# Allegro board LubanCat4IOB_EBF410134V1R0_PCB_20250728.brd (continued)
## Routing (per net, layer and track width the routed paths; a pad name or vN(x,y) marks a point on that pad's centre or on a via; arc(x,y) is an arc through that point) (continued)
MDIP0_PHY: length 30.9
  TOP w0.107: v1(109.33,82.17) 109.48,82.02 109.48,80.75 109.88,80.36 115.88,80.36 117.39,81.87 118.07,81.87 118.88,82.68 120.2,82.68 121.6,84.08 121.6,86.39 121.24,86.76 121.1,86.82 121.06,86.96 J15.2
  BOTTOM w0.107: U14.1 109.83,71.41 109.89,71.47 109.89,71.96 109.52,72.33 109.52,81.99 109.35,82.17 v1(109.33,82.17)
MDIP1_PHY: length 31.2
  TOP w0.107: J15.4 118.81,87.85 118.81,88.95 118.28,89.48 117.15,89.48 117.04,89.38 117.04,89.12 117.12,89.04 117.37,89.04 117.73,88.68 117.73,87.25 119,85.98 119,83.78 117.78,82.57 117.1,82.57 115.59,81.06 111.45,81.06 111.15,81.35 111.15,81.98 v1(110.96,82.17)
  BOTTOM w0.107: v1(110.96,82.17) 111.09,82.04 111.09,82.04 111.08,82.03 111.08,71.3 111.03,71.25 U14.4
MDIP2_PHY: length 23
  TOP w0.107: J15.5 117.16,86.17 117.04,86.21 116.95,86.16 116.62,85.83 116.62,83.07 115.3,81.75 112.85,81.75 112.54,82.06 112.54,82.89 v1(112.37,83.06)
  BOTTOM w0.107: v1(112.37,83.06) 112.5,82.93 112.5,76.58 111.78,75.86 111.78,72.21 111.89,72.1 111.89,71.51 111.83,71.45 U14.6
MDIP3_PHY: length 19.6
  TOP w0.107: v1(114.92,83.16) 114.72,82.95 114.21,82.95 114.05,83.12 114.05,85.86 113.58,86.32 113.57,86.37 113.47,86.42 113.41,86.45 113.36,86.45 113.33,86.49 113.28,86.64 J15.8
  BOTTOM w0.107: U14.9 113.03,71.41 113.11,71.49 113.11,72.07 113.38,72.35 113.38,82.23 114.12,82.97 114.73,82.97 v1(114.92,83.16)
MIC1_L: length 30.7
  BOTTOM w0.203: J27.2 55.12,95.16 55.12,91.18 53.98,90.04 53.15,90.04 J27.4 52.2,86.49 J29.1 50.43,81.67 Z8.2 50.43,78.64 C194.1 50.43,78.33 R208.2 49.41,76.2 47.88,76.2 46.86,75.18 46.86,74.29 C176.2
MIC1_R: length 26
  BOTTOM w0.203: C177.2 46.51,73.93 46.51,75.33 47.73,76.55 48.48,76.55 R218.1 49.14,78.33 C194.2 49.14,78.64 Z11.2 49.14,80.74 49.66,81.25 J29.2 48.64,84.45 48.64,89.33 50.37,91.06 52.07,91.06 J27.3 52.7,91.89 J27.5
MIC2_L: length 19.7
  TOP w0.203: R199.2 57.91,82.43 56.99,81.51 49.36,81.51 49.13,81.28 v1(48.37,81.28)
  BOTTOM w0.203: v1(48.37,81.28) 48.13,81.28 46.81,79.96 46.81,77.42 44.96,75.57 44.96,74.16 C178.2
MIC2_R: length 21.5
  TOP w0.203: R201.2 57.14,81.15 49.5,81.15 49,80.64 48.01,80.64 v1(47.37,81.28)
  BOTTOM w0.203: v1(47.37,81.28) 47.37,81.02 46.46,80.11 46.46,77.57 44.6,75.72 44.6,74.06 C179.2
MINIPCIE_3V3: length 57.6
  TOP w0.254: C151.1 92.26,80.9 87.12,80.9 85.35,79.13 C146.1 R172.1
  TOP w0.381: v1(101.22,80.63) 101.2,80.62 J25.39 ; v1(100.2,80.63) 100.4,80.43 J25.41 ; J25.2 119.2,69.58 119.74,69.04 121.05,69.04 121.59,69.58 121.59,72.87 120.75,73.71 119.2,73.71 v1(118.87,74.04) 118.8,74.12 v1(105.21,74.12)
  TOP w0.508: J25.52 96,71.64 v1(95.25,72.39)
  BOTTOM w0.254: 118.88,74.05 R177.1 ; 118.88,74.05 118.88,73.14 119.75,72.27 C158.1 ; 118.88,74.05 v1(118.87,74.04)
  BOTTOM w0.508: 95.26,72.38 v1(95.25,72.39) ; 95.26,72.38 95.26,72.91 96.39,74.04 96.39,75.71 94.63,77.47 94.63,79.87 v1(95.4,80.64) ; 95.26,72.38 C159.1
  vias: v1(100.2,82.03) v1(101.22,82.03) v1(107.06,72.65) v1(107.85,72.64)
MINIPCIE_NWDISABLE: length 77.4
  TOP w0.152: v1(100.08,64.26) 100.08,65.02 101.09,66.04 102.23,66.04 103.76,67.56 R180.2 ; v1(58.65,81.41) 57.28,80.03 J6.42
  ART03 w0.14: v1(58.65,81.41) 58.65,83.21 60.96,85.52 70.51,85.52 71.64,84.39 97.55,84.39 v1(97.79,84.63)
  BOTTOM w0.152: v1(97.79,84.63) 97.28,84.12 97.28,79.5 100.14,76.65 100.14,64.32 v1(100.08,64.26)
MINIPCIE_PWR_EN: length 92.4
  TOP w0.152: v1(75.95,47.27) 73.79,45.11 73.79,26.67 73.48,26.36 63.98,26.36 63.68,26.06 J5.74
  BOTTOM w0.152: v1(75.95,47.27) 75.95,50.11 75.64,50.42 65.79,50.42 63.63,52.58 63.63,72.35 63.4,72.58 63.4,74.06 63.91,74.56 66.22,74.56 67.44,75.78 67.44,76.67 68,77.23 69.29,77.23 72.7,80.64 73.18,80.64 74.55,82.02 74.55,82.17 75.06,82.68 R175.1
MIPI_CSI0_RX_CLK0N: length 101.5
  TOP w0.107: J3.52 33.71,24.55 33.65,24.49 33.65,23.97 arc(33.68,23.9) 33.76,23.87 arc(33.83,23.84) 33.86,23.76 33.86,23.54 arc(33.83,23.47) 33.76,23.44 arc(33.68,23.41) 33.65,23.34 33.65,23.11 arc(33.68,23.04) 33.76,23.01 arc(33.83,22.98) 33.86,22.91 33.86,22.69 arc(33.83,22.62) 33.76,22.59 arc(33.68,22.56) 33.65,22.48 33.65,21.7 33.89,21.46 34.66,21.46 34.86,21.66 v1(34.86,21.68)
  ART03 w0.102: v1(124.02,24.49) 124.21,24.3 124.21,23.97 123.1,22.86 83.45,22.86 82.43,21.84 41.63,21.84 41.07,22.4 37.36,22.4 36.45,21.48 35.45,21.48 35.26,21.68 v1(34.86,21.68)
  BOTTOM w0.107: v1(124.02,24.49) 124.2,24.68 124.2,26.49 124.46,26.75 J23.10
MIPI_CSI0_RX_CLK0P: length 101.5
  TOP w0.107: v1(34.86,21.01) 34.7,21.18 33.78,21.18 33.37,21.58 33.37,24.49 33.31,24.55 J3.50
  ART03 w0.102: v1(34.86,21.01) 35.26,21.01 35.45,21.21 36.56,21.21 37.48,22.12 40.96,22.12 41.51,21.56 82.55,21.56 83.57,22.58 123.22,22.58 124.49,23.85 124.49,24.3 v1(124.68,24.49)
  BOTTOM w0.107: J23.9 125.72,26.25 125.5,26.47 124.58,26.47 124.49,26.37 124.49,24.68 v1(124.68,24.49)
MIPI_CSI0_RX_CLK1N: length 116.4
  TOP w0.107: J3.36 30.51,26.46 v1(30.67,26.62) ; v1(123.95,29.72) 124.13,29.89 124.77,29.89 125.29,29.37 125.54,29.37 125.66,29.25 J24.10
  ART03 w0.102: v1(30.67,26.62) 30.67,27.01 30.48,27.21 30.48,28.47 30.76,28.75 65.43,28.75 65.7,29.02 65.7,30.05 65.8,30.15 66.1,30.15 66.2,30.05 66.2,29.02 66.47,28.75 67.07,28.75 67.34,29.02 67.34,30.83 67.44,30.94 67.74,30.94 67.84,30.83 67.84,29.02 68.11,28.75 68.66,28.75 68.94,29.03 68.94,30.73 69.14,30.94 69.88,30.94 70.08,30.73 70.08,29.14 70.42,28.8 71.4,28.8 71.79,29.19 71.79,30.8 71.91,30.91 72.21,30.91 72.31,30.81 72.31,30.11 72.57,29.84 73.11,29.84 73.37,30.11 73.37,30.81 73.48,30.91 99.72,30.91 102.04,28.59 107.71,28.59 108.1,28.19 115.13,28.19 117.84,30.91 120.2,30.91 arc(120.26,30.88) 120.29,30.82 arc(120.31,30.76) 120.38,30.73 120.61,30.73 arc(120.67,30.76) 120.7,30.82 arc(120.72,30.88) 120.78,30.91 121.01,30.91 arc(121.08,30.88) 121.1,30.82 arc(121.13,30.76) 121.19,30.73 121.42,30.73 arc(121.48,30.76) 121.51,30.82 arc(121.53,30.88) 121.6,30.91 121.86,30.91 122.81,29.96 123.71,29.96 v1(123.95,29.72)
MIPI_CSI0_RX_CLK1P: length 116.4
  TOP w0.107: J3.34 30.11,26.51 v1(30.01,26.62) ; J24.9 125.66,29.75 125.56,29.65 125.41,29.65 124.89,30.18 124.15,30.18 v1(123.95,30.38)
  ART03 w0.102: v1(30.01,26.62) 30.01,27.01 30.2,27.21 30.2,28.59 30.65,29.03 65.32,29.03 65.42,29.13 65.42,30.16 65.68,30.43 66.22,30.43 66.48,30.16 66.48,29.13 66.59,29.03 66.95,29.03 67.06,29.13 67.06,30.95 67.32,31.22 67.86,31.22 68.12,30.95 68.12,29.13 68.22,29.03 68.54,29.03 68.66,29.15 68.66,30.85 69.02,31.22 69.99,31.22 70.36,30.85 70.36,29.26 70.54,29.08 71.28,29.08 71.51,29.31 71.51,30.91 71.79,31.19 72.32,31.19 72.59,30.92 72.59,30.22 72.69,30.12 72.99,30.12 73.09,30.22 73.09,30.92 73.36,31.19 99.83,31.19 102.15,28.87 107.82,28.87 108.22,28.47 115.01,28.47 117.73,31.19 121.97,31.19 122.92,30.24 123.81,30.24 v1(123.95,30.38)
MIPI_CSI0_RX_D0N: length 101.6
  TOP w0.107: J3.62 35.71,24.55 35.65,24.49 35.65,24.06 36.24,23.47 36.88,23.47 arc(36.95,23.5) 36.98,23.57 arc(37.01,23.64) 37.09,23.67 37.31,23.67 arc(37.38,23.64) 37.41,23.57 arc(37.44,23.5) 37.51,23.47 37.74,23.47 arc(37.81,23.5) 37.84,23.57 arc(37.87,23.64) 37.94,23.67 38.16,23.67 arc(38.23,23.64) 38.26,23.57 arc(38.29,23.5) 38.37,23.47 39.01,23.47 39.2,23.66 v1(39.6,23.66)
  ART03 w0.102: v1(39.6,23.66) 40,23.66 40.19,23.47 41.3,23.47 42.08,22.69 72.76,22.69 72.86,22.79 72.86,23.36 73.13,23.62 73.66,23.62 73.93,23.36 73.93,22.79 74.03,22.69 74.34,22.69 74.44,22.79 74.44,23.36 74.7,23.62 75.24,23.62 75.5,23.36 75.5,22.79 75.61,22.69 81.38,22.69 82.71,24.03 122.69,24.03 122.94,24.27 122.94,25.69 123.46,26.21 125.36,26.21 126.78,27.63 127.46,27.63 v1(127.64,27.81)
  BOTTOM w0.107: J23.12 127.25,27.75 127.34,27.66 127.49,27.66 v1(127.64,27.81)
MIPI_CSI0_RX_D0P: length 101.6
  TOP w0.107: J3.60 35.31,24.55 35.37,24.49 35.37,23.94 36.12,23.18 39.01,23.18 39.2,23 v1(39.6,23)
  ART03 w0.102: v1(127.64,27.15) 127.43,27.35 126.9,27.35 125.48,25.93 123.57,25.93 123.22,25.58 123.22,24.15 122.81,23.75 82.83,23.75 81.49,22.41 75.49,22.41 75.22,22.68 75.22,23.24 75.12,23.34 74.82,23.34 74.72,23.24 74.72,22.68 74.45,22.41 73.92,22.41 73.65,22.68 73.65,23.24 73.55,23.34 73.24,23.34 73.14,23.24 73.14,22.68 72.88,22.41 41.96,22.41 41.19,23.19 40.19,23.19 40,23 v1(39.6,23)
  BOTTOM w0.107: J23.11 127.25,27.25 127.32,27.32 127.47,27.32 v1(127.64,27.15)
MIPI_CSI0_RX_D1N: length 101.5
  TOP w0.107: J3.58 34.91,24.55 34.85,24.49 34.85,23.26 36.78,21.33 37.24,21.33 arc(37.32,21.36) 37.35,21.44 arc(37.38,21.51) 37.45,21.54 37.67,21.54 arc(37.74,21.51) 37.77,21.44 arc(37.8,21.36) 37.87,21.33 38.1,21.33 arc(38.17,21.36) 38.2,21.44 arc(38.23,21.51) 38.3,21.54 38.52,21.54 arc(38.6,21.51) 38.63,21.44 arc(38.66,21.36) 38.73,21.33 39.01,21.33 39.2,21.52 v1(39.6,21.52)
  ART03 w0.102: v1(39.6,21.52) 40,21.52 40.19,21.33 40.89,21.33 41.24,20.98 42.62,20.98 42.88,20.71 42.88,20.19 42.98,20.09 43.29,20.09 43.39,20.19 43.39,20.71 43.66,20.98 83.29,20.98 84.4,22.1 123.65,22.1 125.6,24.05 125.6,24.71 126.48,25.59 127.44,25.59 v1(127.64,25.78)
  BOTTOM w0.107: J23.8 127.25,25.75 127.36,25.65 127.5,25.65 v1(127.64,25.78)
MIPI_CSI0_RX_D1P: length 101.5
  TOP w0.107: J3.56 34.51,24.55 34.57,24.49 34.57,23.14 36.66,21.05 39.01,21.05 39.2,20.86 v1(39.6,20.86)
  ART03 w0.102: v1(39.6,20.86) 40,20.86 40.19,21.05 40.77,21.05 41.12,20.7 42.5,20.7 42.6,20.6 42.6,20.08 42.87,19.81 43.41,19.81 43.67,20.08 43.67,20.6 43.77,20.7 83.4,20.7 84.52,21.82 123.76,21.82 125.88,23.94 125.88,24.6 126.6,25.31 127.44,25.31 v1(127.64,25.12)
  BOTTOM w0.107: J23.7 127.25,25.25 127.31,25.3 127.45,25.3 v1(127.64,25.12)
MIPI_CSI0_RX_D2N: length 116.3
  TOP w0.107: J3.46 32.51,26.34 v1(32.79,26.62) ; J24.12 125.66,28.25 125.55,28.36 124.19,28.36 124,28.17 v1(123.95,28.17)
  ART03 w0.102: v1(32.79,26.62) 32.79,27.01 32.64,27.17 32.64,27.61 32.99,27.96 70.59,27.96 70.69,27.86 70.69,26.25 70.96,25.98 71.5,25.98 71.76,26.25 71.76,27.86 71.86,27.96 72.09,27.96 72.19,27.86 72.19,26.27 72.46,26 72.99,26 73.26,26.27 73.26,27.84 73.36,27.94 73.67,27.94 73.77,27.84 73.77,26.27 74.03,26 74.61,26 74.9,26.29 74.9,29.84 75.08,30.02 98.53,30.02 98.73,29.82 98.73,27.54 99,27.28 99.58,27.28 99.85,27.54 99.85,28.73 99.95,28.83 100.26,28.83 100.36,28.73 100.36,27.54 100.62,27.28 115.54,27.28 115.73,27.46 arc(115.82,27.5) 115.92,27.46 arc(116.02,27.42) 116.11,27.46 116.21,27.56 arc(116.25,27.66) 116.21,27.75 arc(116.17,27.85) 116.21,27.94 118.21,29.95 121.38,29.95 122.96,28.37 123.75,28.37 v1(123.95,28.17)
MIPI_CSI0_RX_D2P: length 116.3
  TOP w0.107: J3.44 32.11,26.6 v1(32.13,26.62) ; v1(123.95,28.83) 124.14,28.64 125.55,28.64 125.66,28.75 J24.11
  ART03 w0.102: v1(32.13,26.62) 32.13,27.05 32.36,27.28 32.36,27.72 32.87,28.24 70.71,28.24 70.97,27.97 70.97,26.36 71.08,26.26 71.38,26.26 71.48,26.36 71.48,27.97 71.75,28.24 72.21,28.24 72.47,27.97 72.47,26.38 72.57,26.28 72.88,26.28 72.98,26.38 72.98,27.95 73.25,28.22 73.78,28.22 74.05,27.95 74.05,26.38 74.15,26.28 74.5,26.28 74.63,26.41 74.63,29.96 74.97,30.3 98.65,30.3 99.01,29.93 99.01,27.66 99.12,27.56 99.47,27.56 99.57,27.66 99.57,28.84 99.84,29.11 100.37,29.11 100.64,28.84 100.64,27.66 100.74,27.56 115.43,27.56 118.1,30.22 121.5,30.22 123.07,28.65 123.77,28.65 v1(123.95,28.83)
MIPI_CSI0_RX_D3N: length 116.3
  TOP w0.107: v1(31.84,22.55) 31.84,22.95 31.65,23.13 31.65,24.49 31.71,24.55 J3.42 ; J24.8 127.26,30.25 127.38,30.37 128.1,30.37 v1(128.27,30.2)
  ART03 w0.102: v1(128.27,30.2) 128.08,30.39 126.31,30.39 124.88,31.83 124.62,31.83 arc(124.55,31.8) 124.52,31.72 arc(124.49,31.65) 124.41,31.62 124.21,31.62 arc(124.14,31.65) 124.11,31.72 arc(124.08,31.8) 124.01,31.83 123.8,31.83 arc(123.73,31.8) 123.7,31.72 arc(123.67,31.65) 123.6,31.62 123.4,31.62 arc(123.33,31.65) 123.3,31.72 arc(123.27,31.8) 123.2,31.83 117.23,31.83 114.87,29.46 102.45,29.46 100.19,31.72 66.03,31.72 63.95,29.64 30.47,29.64 29.26,28.44 29.26,24.91 29.46,24.7 31.29,24.7 31.65,24.34 31.65,23.14 31.84,22.94 v1(31.84,22.55)
MIPI_CSI0_RX_D3P: length 116.3
  TOP w0.107: J3.40 31.31,24.55 31.37,24.49 31.37,23.13 31.18,22.95 v1(31.18,22.55) ; v1(128.27,30.86) 128.06,30.65 127.35,30.65 127.26,30.75 J24.7
  ART03 w0.102: v1(31.18,22.55) 31.18,22.94 31.37,23.14 31.37,24.22 31.17,24.42 29.35,24.42 28.98,24.79 28.98,28.55 30.35,29.92 63.83,29.92 65.91,32 100.3,32 102.56,29.74 114.75,29.74 117.12,32.1 124.99,32.1 126.43,30.67 128.08,30.67 v1(128.27,30.86)
MIPI_DPHY0_RX_CLKN: length 128.4
  TOP w0.107: v1(22.5,59.94) 22.5,60.34 22.32,60.53 22.32,65.57 26.45,69.7 26.45,70.95 26.51,71.01 J4.15
  ART03 w0.102: v1(121.54,52.32) 121.39,52.48 121.39,52.53 121.28,52.64 121.28,53.72 119.25,55.75 118.89,55.75 arc(118.82,55.78) 118.8,55.85 arc(118.77,55.91) 118.7,55.94 118.48,55.94 arc(118.42,55.91) 118.39,55.85 arc(118.36,55.78) 118.3,55.75 118.08,55.75 arc(118.01,55.78) 117.98,55.85 arc(117.96,55.91) 117.89,55.94 117.67,55.94 arc(117.6,55.91) 117.58,55.85 arc(117.55,55.78) 117.48,55.75 105.69,55.75 103.91,57.53 85.36,57.53 84.44,56.62 80.47,56.62 78.49,58.6 53.57,58.6 52.2,59.97 46.49,59.97 44.82,58.29 22.75,58.29 22.35,58.69 22.35,59.79 v1(22.5,59.94)
  BOTTOM w0.107: v1(121.54,52.32) 121.31,52.1 121.31,49.45 122.17,48.59 125.5,48.59 125.66,48.75 J21.10
MIPI_DPHY0_RX_CLKP: length 128.3
  TOP w0.107: J4.13 26.11,71.01 26.17,70.95 26.17,69.82 22.03,65.68 22.03,60.53 21.84,60.34 v1(21.84,59.94)
  ART03 w0.102: v1(120.88,52.32) 121.01,52.45 121.01,53.6 119.14,55.47 105.57,55.47 103.8,57.25 85.47,57.25 84.56,56.34 80.35,56.34 78.37,58.32 53.46,58.32 52.09,59.69 46.61,59.69 44.93,58.01 22.63,58.01 22.07,58.57 22.07,59.71 v1(21.84,59.94)
  BOTTOM w0.107: v1(120.88,52.32) 121.03,52.17 121.03,49.33 122.05,48.31 125.6,48.31 125.66,48.25 J21.9
MIPI_DPHY0_RX_D0N: length 128.4
  TOP w0.107: J4.25 28.51,71.01 28.45,70.95 28.45,69.56 25.03,66.13 25.03,63.8 24.74,63.51 24.74,59.68 24.95,59.46 27.05,59.46 27.33,59.19 27.33,58.63 27.05,58.36 25.58,58.36 25.4,58.18 25.4,57.32 25.61,57.11 27.01,57.11 v1(27.18,57.28)
  ART03 w0.102: v1(27.18,57.28) 27.36,57.1 45.18,57.1 46.38,58.29 52.29,58.29 53.22,57.36 74.55,57.36 76.08,55.83 77.68,55.83 77.78,55.93 77.78,56.86 78.05,57.12 78.59,57.12 78.85,56.86 78.85,55.93 78.95,55.83 104.2,55.83 105.12,54.91 117.61,54.91 118.58,53.94 arc(118.65,53.91) 118.73,53.94 arc(118.8,53.98) 118.88,53.94 119.02,53.81 arc(119.05,53.73) 119.02,53.66 arc(118.98,53.58) 119.02,53.5 119.15,53.37 arc(119.23,53.34) 119.3,53.37 arc(119.38,53.4) 119.46,53.37 119.59,53.24 arc(119.62,53.16) 119.59,53.08 arc(119.56,53.01) 119.59,52.93 121.16,51.36 121.16,50.75 121.39,50.53 121.97,50.53 v1(122.19,50.74)
  BOTTOM w0.107: J21.12 125.66,49.75 125.55,49.64 123.75,49.64 122.84,50.55 122.37,50.55 v1(122.19,50.74)
MIPI_DPHY0_RX_D0P: length 128.4
  TOP w0.107: v1(27.18,56.62) 27.18,56.63 26.98,56.83 25.5,56.83 25.12,57.21 25.12,58.3 25.46,58.65 26.93,58.65 27.04,58.75 27.04,59.07 26.93,59.18 24.84,59.18 24.46,59.56 24.46,63.63 24.74,63.92 24.74,66.25 28.17,69.67 28.17,70.95 28.11,71.01 J4.23
  ART03 w0.102: v1(122.19,50.08) 122.02,50.25 121.28,50.25 120.88,50.64 120.88,51.24 117.49,54.63 105,54.63 104.09,55.55 78.84,55.55 78.57,55.81 78.57,56.74 78.47,56.84 78.16,56.84 78.06,56.74 78.06,55.81 77.8,55.55 75.97,55.55 74.44,57.08 53.11,57.08 52.17,58.01 46.49,58.01 45.3,56.82 27.36,56.82 27.18,56.63 v1(27.18,56.62)
  BOTTOM w0.107: v1(122.19,50.08) 122.37,50.27 122.72,50.27 123.63,49.36 125.55,49.36 125.66,49.25 J21.11
MIPI_DPHY0_RX_D1N: length 128.3
  TOP w0.107: v1(24,56.77) 24,57.17 23.8,57.37 23.8,65.97 27.71,69.89 J4.21
  ART03 w0.102: v1(24,56.77) 23.83,56.59 23.83,56.15 23.99,55.99 24.71,55.99 24.81,56.09 24.81,56.82 25.08,57.08 25.61,57.08 25.88,56.82 25.88,56.09 25.98,55.99 45.82,55.99 47.23,57.4 51.73,57.4 52.61,56.52 74.17,56.52 76.09,54.61 104.09,54.61 104.62,54.08 117.37,54.08 120.02,51.43 120.02,51.12 v1(120.21,50.93)
  BOTTOM w0.107: v1(120.21,50.93) 120.04,50.76 120.04,49.22 121.64,47.62 123.58,47.62 arc(123.66,47.65) 123.69,47.73 arc(123.72,47.81) 123.8,47.84 124,47.84 arc(124.08,47.81) 124.12,47.73 arc(124.15,47.65) 124.23,47.62 124.43,47.62 arc(124.51,47.65) 124.54,47.73 arc(124.58,47.81) 124.66,47.84 124.86,47.84 arc(124.94,47.81) 124.97,47.73 arc(125,47.65) 125.08,47.62 125.54,47.62 125.68,47.75 J21.8
MIPI_DPHY0_RX_D1P: length 128.3
  TOP w0.107: v1(23.34,56.77) 23.34,57.17 23.51,57.34 23.51,66.09 27.43,70 27.43,70.89 27.31,71.01 J4.19
  ART03 w0.102: v1(23.34,56.77) 23.55,56.56 23.55,56.03 23.87,55.71 24.82,55.71 25.09,55.97 25.09,56.7 25.19,56.8 25.5,56.8 25.6,56.7 25.6,55.97 25.86,55.71 45.93,55.71 47.35,57.12 51.61,57.12 52.49,56.24 74.06,56.24 75.97,54.33 103.97,54.33 104.51,53.8 117.26,53.8 119.74,51.32 119.74,51.12 v1(119.55,50.93)
  BOTTOM w0.107: J21.7 125.66,47.25 125.58,47.33 121.53,47.33 119.76,49.1 119.76,50.71 v1(119.55,50.93)
MIPI_DPHY0_RX_D2N: length 128.2
  TOP w0.107: J4.9 25.31,71.01 25.25,70.95 25.25,70.08 20.55,65.38 20.55,62.15 v1(20.73,61.97)
  ART03 w0.102: v1(122.81,53.21) 122.58,53.44 122.58,54.96 120.88,56.67 120.21,56.67 arc(120.13,56.7) 120.1,56.77 arc(120.07,56.84) 120,56.87 119.8,56.87 arc(119.73,56.84) 119.69,56.77 arc(119.66,56.7) 119.59,56.67 119.39,56.67 arc(119.32,56.7) 119.29,56.77 arc(119.26,56.84) 119.18,56.87 118.99,56.87 arc(118.91,56.84) 118.88,56.77 arc(118.85,56.7) 118.78,56.67 106.14,56.67 104.31,58.5 85.64,58.5 84.58,59.56 56.87,59.56 56.77,59.66 56.77,60.53 56.51,60.8 55.97,60.8 55.71,60.53 55.71,59.66 55.6,59.56 54.64,59.56 54.44,59.77 54.44,60.49 54.07,60.86 45.7,60.86 43.93,59.08 24.63,59.08 22.9,60.8 20.75,60.8 20.55,61 20.55,61.8 v1(20.73,61.97)
  BOTTOM w0.107: v1(122.81,53.21) 122.63,53.04 122.63,52.63 123.12,52.14 125.57,52.14 125.68,52.25 J21.17
MIPI_DPHY0_RX_D2P: length 128.2
  TOP w0.107: J4.7 24.91,71.01 24.97,70.95 24.97,70.2 20.27,65.5 20.27,62.18 v1(20.07,61.97)
  ART03 w0.102: v1(20.07,61.97) 20.27,61.77 20.27,60.89 20.64,60.52 22.79,60.52 24.51,58.8 44.04,58.8 45.82,60.58 53.95,60.58 54.16,60.37 54.16,59.65 54.52,59.28 55.72,59.28 55.99,59.55 55.99,60.42 56.09,60.52 56.39,60.52 56.49,60.42 56.49,59.55 56.76,59.28 84.46,59.28 85.53,58.22 104.19,58.22 106.02,56.39 120.76,56.39 122.3,54.85 122.3,53.36 v1(122.15,53.21)
  BOTTOM w0.107: v1(122.15,53.21) 122.35,53.01 122.35,52.49 122.99,51.85 125.57,51.85 125.67,51.75 J21.16
MIPI_DPHY0_RX_D3N: length 128.3
  TOP w0.107: J4.5 24.51,71.01 24.45,70.95 24.45,70.5 24.07,70.12 22.88,70.12 22.38,69.62 22.38,68.45 19.56,65.63 19.56,64.51 v1(19.76,64.31)
  ART03 w0.102: v1(124.13,54.23) 123.94,54.42 123.94,55.83 123.42,56.35 122.75,56.35 121.45,57.64 120.76,57.64 arc(120.68,57.68) 120.65,57.76 arc(120.61,57.84) 120.53,57.88 120.36,57.88 arc(120.27,57.84) 120.24,57.76 arc(120.21,57.68) 120.12,57.64 106.6,57.64 104.4,59.84 86.25,59.84 85.45,60.64 60.07,60.64 59.08,61.63 45.22,61.63 43.43,59.84 25.24,59.84 24.16,60.92 24.16,61.06 24.57,61.47 24.57,61.84 24.19,62.22 23.82,62.22 23.35,61.75 23.18,61.75 22.98,61.96 22.98,62.1 23.46,62.58 23.46,62.96 23.08,63.34 22.7,63.34 22.29,62.93 22.15,62.93 21.45,63.63 19.83,63.63 19.56,63.89 19.56,64.11 v1(19.76,64.31)
  BOTTOM w0.107: v1(124.13,54.23) 124.11,54.23 123.85,53.96 123.85,53.68 123.99,53.53 125.49,53.53 125.71,53.75 J21.20
MIPI_DPHY0_RX_D3P: length 128.3
  TOP w0.107: J4.3 24.11,71.01 24.17,70.95 24.17,70.62 23.96,70.41 22.76,70.41 22.09,69.74 22.09,68.57 19.27,65.75 19.27,64.47 19.11,64.31 v1(19.1,64.31)
  ART03 w0.102: v1(123.47,54.23) 123.66,54.42 123.66,55.72 123.31,56.07 122.63,56.07 121.34,57.36 106.48,57.36 104.28,59.56 86.13,59.56 85.33,60.36 59.96,60.36 58.96,61.36 45.34,61.36 43.55,59.56 25.12,59.56 23.88,60.8 23.88,61.18 24.29,61.58 24.29,61.73 24.08,61.94 23.93,61.94 23.46,61.47 23.07,61.47 22.7,61.84 22.7,62.22 23.18,62.7 23.18,62.84 22.96,63.06 22.82,63.06 22.41,62.65 22.03,62.65 21.34,63.35 19.71,63.35 19.28,63.78 19.28,64.13 v1(19.1,64.31)
  BOTTOM w0.107: J21.19 123.88,53.25 123.57,53.56 123.57,54.13 v1(123.47,54.23)
MIPI_DPHY0_TX_CLKN: length 125.2
  TOP w0.107: v1(27.59,62.38) 27.99,62.38 28.18,62.57 28.54,62.57 28.81,62.84 28.81,66.12 31.65,68.97 31.65,70.95 31.71,71.01 J4.41
  ART03 w0.102: v1(128.91,69.7) 128.71,69.89 127.45,69.89 125.23,67.66 93.27,67.66 92.87,67.26 92.87,64.61 92.53,64.27 68.78,64.27 68.51,64.53 68.51,65.23 68.41,65.33 68.11,65.33 68.01,65.23 68.01,64.53 67.74,64.27 67.2,64.27 66.94,64.53 66.94,65.23 66.84,65.33 66.53,65.33 66.43,65.23 66.43,64.53 66.17,64.27 64.19,64.27 63.93,64.53 63.93,65.05 63.83,65.16 63.52,65.16 63.42,65.05 63.42,64.53 63.15,64.27 62.42,64.27 61.78,64.91 48.3,64.91 48,64.61 32.1,64.61 30.07,62.58 27.8,62.58 v1(27.59,62.38)
  BOTTOM w0.107: J19.24 127.31,69.74 127.43,69.86 128.74,69.86 v1(128.91,69.7)
MIPI_DPHY0_TX_CLKP: length 125.3
  TOP w0.107: J4.39 31.31,71.01 31.37,70.95 31.37,69.09 28.52,66.24 28.52,62.96 28.42,62.85 28.18,62.85 27.99,63.04 v1(27.59,63.04)
  ART03 w0.102: v1(27.59,63.04) 27.76,62.86 29.96,62.86 31.98,64.89 47.88,64.89 48.18,65.19 61.9,65.19 62.54,64.55 63.04,64.55 63.14,64.65 63.14,65.17 63.41,65.43 63.94,65.43 64.21,65.17 64.21,64.65 64.31,64.55 66.05,64.55 66.15,64.65 66.15,65.35 66.42,65.61 66.95,65.61 67.22,65.35 67.22,64.65 67.32,64.55 67.63,64.55 67.73,64.65 67.73,65.35 67.99,65.61 68.53,65.61 68.79,65.35 68.79,64.65 68.9,64.55 92.41,64.55 92.59,64.72 92.59,67.38 93.15,67.94 118.8,67.94 arc(118.88,67.98) 118.91,68.05 arc(118.94,68.13) 119.02,68.16 119.21,68.16 arc(119.28,68.13) 119.31,68.05 arc(119.35,67.98) 119.42,67.94 119.61,67.94 arc(119.69,67.98) 119.72,68.05 arc(119.75,68.13) 119.83,68.16 120.02,68.16 arc(120.1,68.13) 120.13,68.05 arc(120.16,67.98) 120.24,67.94 125.12,67.94 127.34,70.17 128.71,70.17 v1(128.91,70.36)
  BOTTOM w0.107: v1(128.91,70.36) 128.7,70.15 127.4,70.15 127.31,70.24 J19.23
MIPI_DPHY0_TX_D0N: length 125.2
  TOP w0.107: J4.51 33.71,71.01 33.65,70.95 33.65,68.56 31.88,66.78 31.88,62.29 v1(32.06,62.1)
  ART03 w0.102: v1(32.06,62.1) 31.89,62.28 31.89,63.31 32,63.42 32.8,63.42 32.93,63.29 32.93,61.76 33.24,61.46 34.01,61.46 34.43,61.87 34.43,63.43 34.64,63.64 35.29,63.64 35.48,63.45 35.48,61.81 35.85,61.44 36.81,61.44 37.18,61.81 37.18,63.21 37.31,63.34 40.76,63.34 41.34,63.92 60.84,63.92 61.91,62.85 68.48,62.85 68.9,63.27 87.92,63.27 88.02,63.17 88.02,62.51 88.29,62.25 88.82,62.25 89.09,62.51 89.09,63.17 89.19,63.27 93.43,63.27 93.9,63.75 93.9,66.18 94.11,66.38 99.65,66.38 100,66.73 107.5,66.73 108,66.23 113.33,66.23 113.69,66.58 121.14,66.58 arc(121.21,66.55) 121.24,66.48 arc(121.27,66.41) 121.34,66.38 121.54,66.38 arc(121.61,66.41) 121.64,66.48 arc(121.67,66.55) 121.75,66.58 121.95,66.58 arc(122.02,66.55) 122.05,66.48 arc(122.08,66.41) 122.15,66.38 122.36,66.38 arc(122.43,66.41) 122.46,66.48 arc(122.49,66.55) 122.56,66.58 125.65,66.58 127.42,68.35 128.71,68.35 v1(128.91,68.16)
  BOTTOM w0.107: J19.27 127.31,68.24 127.41,68.35 128.71,68.35 v1(128.91,68.16)
MIPI_DPHY0_TX_D0P: length 125.2
  TOP w0.107: J4.49 33.31,71.01 33.37,70.95 33.37,68.68 31.59,66.9 31.59,62.29 v1(31.4,62.1)
  ART03 w0.102: v1(31.4,62.1) 31.61,62.31 31.61,63.42 31.89,63.7 32.91,63.7 33.21,63.4 33.21,61.88 33.36,61.74 33.9,61.74 34.15,61.98 34.15,63.55 34.52,63.92 35.4,63.92 35.76,63.57 35.76,61.92 35.96,61.72 36.7,61.72 36.9,61.92 36.9,63.33 37.2,63.62 40.64,63.62 41.22,64.2 60.96,64.2 62.03,63.13 68.37,63.13 68.78,63.55 88.04,63.55 88.3,63.28 88.3,62.63 88.4,62.53 88.71,62.53 88.81,62.63 88.81,63.28 89.07,63.55 93.31,63.55 93.62,63.86 93.62,66.3 93.99,66.66 99.54,66.66 99.88,67.01 107.61,67.01 108.12,66.51 113.22,66.51 113.57,66.86 125.54,66.86 127.3,68.63 128.71,68.63 v1(128.91,68.82)
  BOTTOM w0.107: J19.26 127.31,68.74 127.41,68.64 128.72,68.64 v1(128.91,68.82)
MIPI_DPHY0_TX_D1N: length 125.3
  TOP w0.107: v1(30.48,64.13) 30.48,64.53 30.29,64.72 30.29,66.3 32.85,68.87 32.85,70.95 32.91,71.01 J4.47
  ART03 w0.102: v1(128.91,71.22) 128.74,71.39 127.41,71.39 124.78,68.76 124.4,68.76 arc(124.32,68.73) 124.28,68.65 arc(124.25,68.56) 124.17,68.53 123.99,68.53 arc(123.91,68.56) 123.88,68.65 arc(123.84,68.73) 123.76,68.76 123.59,68.76 arc(123.5,68.73) 123.47,68.65 arc(123.44,68.56) 123.35,68.53 123.18,68.53 arc(123.1,68.56) 123.06,68.65 arc(123.03,68.73) 122.95,68.76 91.74,68.76 91.4,68.42 91.4,65.5 91.13,65.23 87.16,65.23 86.9,65.5 86.9,65.83 86.79,65.93 86.45,65.93 86.35,65.83 86.35,65.44 86.09,65.18 85.55,65.18 85.28,65.44 85.28,65.89 85.22,65.95 84.88,65.95 84.78,65.85 84.78,65.44 84.51,65.18 83.98,65.18 83.71,65.44 83.71,65.88 83.64,65.95 83.3,65.95 83.2,65.85 83.2,65.44 82.94,65.18 82.4,65.18 82.14,65.44 82.14,65.86 82.07,65.92 81.73,65.92 81.63,65.82 81.63,65.44 81.36,65.18 80.83,65.18 80.56,65.44 80.56,65.83 80.49,65.89 80.15,65.89 80.05,65.79 80.05,65.44 79.79,65.18 78.91,65.18 78.65,65.44 78.65,65.86 78.58,65.93 78.24,65.93 78.14,65.83 78.14,65.44 77.88,65.18 77.34,65.18 77.07,65.44 77.07,65.84 76.97,65.94 76.7,65.94 76.6,65.84 76.6,65.5 76.34,65.23 75.57,65.23 75.3,65.5 75.3,65.79 75.2,65.89 74.89,65.89 74.79,65.79 74.79,65.5 74.53,65.23 69.85,65.23 69.02,66.06 30.51,66.06 30.28,65.84 30.28,64.34 v1(30.48,64.13)
  BOTTOM w0.107: v1(128.91,71.22) 128.75,71.38 127.44,71.38 127.31,71.24 J19.21
MIPI_DPHY0_TX_D1P: length 125.2
  TOP w0.107: v1(29.82,64.13) 29.82,64.53 30.01,64.72 30.01,66.42 32.57,68.98 32.57,70.95 32.51,71.01 J4.45
  ART03 w0.102: v1(128.91,71.88) 128.69,71.67 127.29,71.67 124.67,69.04 91.63,69.04 91.12,68.53 91.12,65.61 91.02,65.51 87.28,65.51 87.17,65.61 87.17,65.94 86.91,66.21 86.34,66.21 86.07,65.94 86.07,65.56 85.97,65.45 85.67,65.45 85.56,65.56 85.56,66 85.33,66.23 84.76,66.23 84.5,65.97 84.5,65.56 84.4,65.45 84.09,65.45 83.99,65.56 83.99,66 83.76,66.23 83.19,66.23 82.92,65.96 82.92,65.56 82.82,65.45 82.52,65.45 82.41,65.56 82.41,65.97 82.18,66.2 81.61,66.2 81.35,65.94 81.35,65.56 81.25,65.45 80.94,65.45 80.84,65.56 80.84,65.94 80.61,66.17 80.04,66.17 79.77,65.91 79.77,65.56 79.67,65.45 79.03,65.45 78.93,65.56 78.93,65.98 78.7,66.21 78.13,66.21 77.86,65.94 77.86,65.56 77.76,65.45 77.46,65.45 77.35,65.56 77.35,65.95 77.09,66.22 76.59,66.22 76.32,65.95 76.32,65.61 76.22,65.51 75.68,65.51 75.58,65.61 75.58,65.91 75.31,66.17 74.78,66.17 74.51,65.91 74.51,65.61 74.41,65.51 69.97,65.51 69.13,66.34 30.39,66.34 30,65.95 30,64.31 v1(29.82,64.13)
  BOTTOM w0.107: J19.20 127.31,71.74 127.39,71.66 128.69,71.66 v1(128.91,71.88)
MIPI_DPHY0_TX_D2N: length 125.2
  TOP w0.107: J4.35 30.51,71.01 30.45,70.95 30.45,69.06 27.27,65.88 27.27,64.72 27.46,64.53 v1(27.46,64.13)
  ART03 w0.102: v1(27.46,64.13) 27.3,64.29 27.3,67.22 27.43,67.34 27.74,67.34 27.84,67.24 27.84,65.78 28.1,65.51 28.64,65.51 28.91,65.78 28.91,67.24 29.01,67.34 46.03,67.34 46.78,68.08 49.82,68.08 50.44,67.47 69.23,67.47 70.05,66.64 87.66,66.64 87.96,66.34 90.01,66.34 90.46,66.8 90.46,69.4 90.92,69.85 96.02,69.85 96.5,70.33 122.54,70.33 arc(122.61,70.3) 122.64,70.23 arc(122.67,70.16) 122.74,70.13 122.95,70.13 arc(123.02,70.16) 123.05,70.23 arc(123.08,70.3) 123.15,70.33 123.35,70.33 arc(123.42,70.3) 123.45,70.23 arc(123.48,70.16) 123.56,70.13 123.76,70.13 arc(123.83,70.16) 123.86,70.23 arc(123.89,70.3) 123.96,70.33 124.91,70.33 127.43,72.85 128.71,72.85 v1(128.91,72.66)
  BOTTOM w0.107: J19.18 127.31,72.74 127.41,72.85 128.72,72.85 v1(128.91,72.66)
MIPI_DPHY0_TX_D2P: length 125.3
  TOP w0.107: v1(26.8,64.13) 26.8,64.53 26.98,64.72 26.98,65.99 30.17,69.18 30.17,70.95 30.11,71.01 J4.33
  ART03 w0.102: v1(128.91,73.32) 128.71,73.13 127.32,73.13 124.8,70.61 96.38,70.61 95.9,70.13 90.8,70.13 90.19,69.51 90.19,66.91 89.9,66.62 88.07,66.62 87.77,66.92 70.16,66.92 69.34,67.75 50.55,67.75 49.94,68.36 46.66,68.36 45.92,67.62 28.89,67.62 28.63,67.35 28.63,65.89 28.52,65.79 28.22,65.79 28.12,65.89 28.12,67.35 27.85,67.62 27.31,67.62 27.03,67.33 27.03,64.36 v1(26.8,64.13)
  BOTTOM w0.107: J19.17 127.31,73.24 127.41,73.14 128.72,73.14 v1(128.91,73.32)
MIPI_DPHY0_TX_D3N: length 125.2
  TOP w0.107: v1(26.7,60.96) 26.7,61.36 26.51,61.54 26.51,63.28 25.96,63.83 25.96,65.63 29.71,69.39 J4.31
  ART03 w0.102: v1(128.91,66.63) 128.71,66.82 127.28,66.82 125.74,65.28 119.14,65.28 arc(119.07,65.25) 119.04,65.18 arc(119.01,65.1) 118.94,65.07 118.74,65.07 arc(118.66,65.1) 118.63,65.18 arc(118.6,65.25) 118.53,65.28 118.33,65.28 arc(118.26,65.25) 118.23,65.18 arc(118.2,65.1) 118.13,65.07 117.92,65.07 arc(117.85,65.1) 117.82,65.18 arc(117.79,65.25) 117.72,65.28 108.14,65.28 107.64,64.77 95.13,64.77 94.84,64.48 94.84,61.88 94.33,61.37 87.63,61.37 87.05,61.95 70.47,61.95 69.93,61.41 61.61,61.41 60.15,62.86 41.89,62.86 41.51,62.48 41.51,61.73 40.45,60.67 28.27,60.67 27.37,61.57 26.6,61.57 26.5,61.47 26.5,61.15 v1(26.7,60.96)
  BOTTOM w0.107: v1(128.91,66.63) 128.7,66.83 127.39,66.83 127.31,66.74 J19.30
MIPI_DPHY0_TX_D3P: length 125.2
  TOP w0.107: J4.29 29.31,71.01 29.43,70.89 29.43,69.5 25.67,65.75 25.67,63.71 26.22,63.16 26.22,61.54 26.04,61.36 v1(26.04,60.96)
  ART03 w0.102: v1(128.91,67.29) 128.71,67.1 127.17,67.1 125.63,65.56 108.02,65.56 107.52,65.05 95.02,65.05 94.56,64.6 94.56,61.99 94.21,61.64 87.75,61.64 87.16,62.23 70.35,62.23 69.81,61.69 61.72,61.69 60.26,63.14 41.77,63.14 41.23,62.6 41.23,61.84 40.34,60.95 28.38,60.95 27.48,61.85 26.49,61.85 26.22,61.58 26.22,61.15 v1(26.04,60.96)
  BOTTOM w0.107: v1(128.91,67.29) 128.73,67.11 127.44,67.11 127.31,67.24 J19.29
MIPI_DPHY1_RX_CLKN: length 125.2
  TOP w0.107: J4.87 40.91,71.01 40.85,70.95 40.85,69.68 39.06,67.89 37.54,67.89 35.77,66.12 35.77,53.93 arc(35.8,53.84) 35.89,53.8 arc(35.98,53.77) 36.01,53.68 36.01,53.5 arc(35.98,53.41) 35.89,53.38 arc(35.8,53.34) 35.77,53.26 35.77,52.91 v1(35.97,52.7) ; v1(124.56,50.3) 124.4,50.46 124.4,51.75 124.61,51.96 124.93,51.96 125.64,51.25 J22.10
  ART03 w0.102: v1(124.56,50.3) 124.36,50.1 124.36,49.14 123.93,48.72 119.66,48.72 115.71,52.67 114.86,52.67 114.76,52.57 114.76,51.92 114.49,51.66 113.96,51.66 113.69,51.92 113.69,52.57 113.59,52.67 113.28,52.67 113.18,52.57 113.18,51.99 112.92,51.72 112.38,51.72 112.12,51.99 112.12,52.57 112.01,52.67 111.71,52.67 111.61,52.57 111.61,52 111.34,51.74 110.81,51.74 110.54,52 110.54,52.57 110.44,52.67 75.77,52.67 73.6,54.84 47.79,54.84 47.3,54.35 35.98,54.35 35.68,54.06 35.68,53 v1(35.97,52.7)
MIPI_DPHY1_RX_CLKP: length 125.2
  TOP w0.107: J4.85 40.51,71.01 40.57,70.95 40.57,69.8 38.94,68.17 37.42,68.17 35.48,66.24 35.48,52.88 v1(35.31,52.7) ; v1(123.9,50.3) 123.95,50.36 124.01,50.36 124.11,50.46 124.11,51.86 124.49,52.24 125.05,52.24 125.54,51.75 J22.9
  ART03 w0.102: v1(35.31,52.7) 35.4,52.79 35.4,54.17 35.86,54.63 47.19,54.63 47.67,55.12 73.72,55.12 75.89,52.95 110.55,52.95 110.82,52.68 110.82,52.12 110.92,52.02 111.23,52.02 111.33,52.12 111.33,52.68 111.59,52.95 112.13,52.95 112.39,52.68 112.39,52.1 112.5,52 112.8,52 112.9,52.1 112.9,52.68 113.17,52.95 113.7,52.95 113.97,52.68 113.97,52.04 114.07,51.94 114.38,51.94 114.48,52.04 114.48,52.68 114.74,52.95 115.82,52.95 119.77,49 123.82,49 124.08,49.26 124.08,50.12 v1(123.9,50.3)
MIPI_DPHY1_RX_D0N: length 125.3
  TOP w0.107: v1(127.95,48.9) 128.14,49.09 128.14,50.14 127.92,50.35 127.31,50.35 127.21,50.25 J22.12 ; J4.95 42.51,71.01 42.45,70.95 42.45,69 39.88,66.42 38.96,66.42 38.31,65.76 38.31,61.99 arc(38.34,61.91) 38.43,61.87 arc(38.51,61.84) 38.55,61.75 38.55,61.56 arc(38.51,61.48) 38.43,61.44 arc(38.34,61.41) 38.31,61.33 38.31,61.14 arc(38.34,61.05) 38.43,61.02 arc(38.51,60.98) 38.55,60.9 38.55,60.71 arc(38.51,60.63) 38.43,60.59 arc(38.34,60.56) 38.31,60.47 38.31,60.28 arc(38.34,60.2) 38.43,60.16 arc(38.51,60.13) 38.55,60.05 38.55,59.86 arc(38.51,59.77) 38.43,59.74 arc(38.34,59.7) 38.31,59.62 38.31,59.43 arc(38.34,59.35) 38.43,59.31 arc(38.51,59.28) 38.55,59.19 38.55,59 arc(38.51,58.92) 38.43,58.88 arc(38.34,58.85) 38.31,58.77 38.31,55.98 39.32,54.96 39.32,54.15 arc(39.36,54.04) 39.47,54 arc(39.58,53.96) 39.62,53.85 39.62,53.73 arc(39.58,53.62) 39.47,53.57 arc(39.36,53.53) 39.32,53.42 39.32,52.91 v1(39.53,52.7)
  ART03 w0.102: v1(39.53,52.7) 39.29,52.46 39.29,52.3 39.44,52.15 42.58,52.15 43.39,52.96 72.43,52.96 74.26,51.13 101.74,51.13 102.04,50.83 102.04,50.27 102.14,50.16 102.79,50.16 102.89,50.27 102.89,50.97 103.16,51.24 103.7,51.24 103.96,50.97 103.96,50.27 104.06,50.16 104.37,50.16 104.47,50.27 104.47,51.02 104.73,51.29 105.27,51.29 105.54,51.02 105.54,50.27 105.64,50.16 105.94,50.16 106.04,50.27 106.04,51.07 106.31,51.33 106.85,51.33 107.11,51.07 107.11,50.27 107.21,50.16 116.55,50.16 119.34,47.37 127.46,47.37 128.1,48.02 128.1,48.75 v1(127.95,48.9)
MIPI_DPHY1_RX_D0P: length 125.2
  TOP w0.107: J22.11 127.17,50.75 127.28,50.64 128.04,50.64 128.42,50.26 128.42,49.09 v1(128.61,48.9) ; J4.93 42.11,71.01 42.17,70.95 42.17,69.11 39.76,66.7 38.85,66.7 38.02,65.88 38.02,55.86 39.03,54.85 39.03,52.87 v1(38.87,52.7)
  ART03 w0.102: v1(128.61,48.9) 128.38,48.68 128.38,47.9 127.57,47.09 119.22,47.09 116.43,49.88 107.1,49.88 106.83,50.15 106.83,50.95 106.73,51.05 106.43,51.05 106.32,50.95 106.32,50.15 106.06,49.88 105.52,49.88 105.26,50.15 105.26,50.91 105.16,51.01 104.85,51.01 104.75,50.91 104.75,50.15 104.48,49.88 103.95,49.88 103.68,50.15 103.68,50.85 103.58,50.96 103.28,50.96 103.17,50.85 103.17,50.15 102.91,49.88 102.03,49.88 101.76,50.15 101.76,50.71 101.63,50.85 74.14,50.85 72.31,52.68 43.51,52.68 42.7,51.87 39.32,51.87 39.01,52.18 39.01,52.56 v1(38.87,52.7)
MIPI_DPHY1_RX_D1N: length 125.2
  TOP w0.107: v1(37.72,53.4) 37.56,53.24 37.19,53.24 37.08,53.34 37.08,53.85 arc(37.12,53.94) 37.21,53.98 arc(37.31,54.01) 37.34,54.11 37.34,54.27 arc(37.31,54.37) 37.21,54.4 arc(37.12,54.44) 37.08,54.53 37.08,55.42 arc(37.12,55.51) 37.21,55.54 arc(37.3,55.58) 37.33,55.67 37.33,55.85 arc(37.3,55.94) 37.21,55.97 arc(37.12,56.01) 37.08,56.1 37.08,56.27 arc(37.12,56.36) 37.21,56.4 arc(37.3,56.43) 37.33,56.52 37.33,56.7 arc(37.3,56.79) 37.21,56.82 arc(37.12,56.86) 37.08,56.95 37.08,57.13 arc(37.12,57.22) 37.21,57.25 arc(37.3,57.29) 37.33,57.38 37.33,57.55 arc(37.3,57.64) 37.21,57.68 arc(37.12,57.71) 37.08,57.8 37.08,57.98 arc(37.12,58.07) 37.21,58.11 arc(37.3,58.14) 37.33,58.23 37.33,58.41 arc(37.3,58.5) 37.21,58.53 arc(37.12,58.57) 37.08,58.66 37.08,65.85 38.43,67.19 39.63,67.19 41.65,69.21 41.65,70.95 41.71,71.01 J4.91 ; v1(128.18,52.02) 127.93,52.27 126.48,52.27 J22.8
  ART03 w0.102: v1(37.72,53.4) 37.93,53.19 38.2,53.19 38.73,53.72 73.56,53.72 75.26,52.02 107.73,52.02 108.04,51.71 108.04,51.22 108.18,51.08 108.79,51.08 108.89,51.18 108.89,51.85 109.16,52.11 109.69,52.11 109.96,51.85 109.96,51.18 110.06,51.08 116.68,51.08 119.6,48.16 125.04,48.16 125.25,48.36 125.25,49.16 125.61,49.53 126.75,49.53 126.85,49.63 126.85,49.94 126.75,50.04 126.24,50.04 125.92,50.35 125.92,50.95 126.26,51.28 127.21,51.28 arc(127.29,51.32) 127.33,51.4 arc(127.36,51.48) 127.44,51.51 127.62,51.51 arc(127.7,51.48) 127.73,51.4 arc(127.77,51.32) 127.85,51.28 128.17,51.28 128.36,51.47 128.36,51.84 v1(128.18,52.02)
MIPI_DPHY1_RX_D1P: length 125.2
  TOP w0.107: J4.89 41.31,71.01 41.37,70.95 41.37,69.33 39.52,67.48 38.31,67.48 36.8,65.96 36.8,53.23 37.07,52.95 37.51,52.95 v1(37.72,52.74) ; J22.7 127.18,52.75 127.37,52.56 128.06,52.56 v1(128.18,52.68)
  ART03 w0.102: v1(37.72,52.74) 37.89,52.91 38.32,52.91 38.85,53.44 73.44,53.44 75.14,51.74 107.62,51.74 107.76,51.59 107.76,51.1 108.07,50.8 108.91,50.8 109.17,51.06 109.17,51.73 109.27,51.84 109.58,51.84 109.68,51.73 109.68,51.06 109.95,50.8 116.56,50.8 119.48,47.88 125.16,47.88 125.53,48.24 125.53,49.05 125.73,49.25 126.87,49.25 127.13,49.51 127.13,50.05 126.87,50.32 126.35,50.32 126.2,50.47 126.2,50.83 126.38,51 128.29,51 128.64,51.35 128.64,52.22 v1(128.18,52.68)
MIPI_DPHY1_RX_D2N: length 125.1
  TOP w0.107: v1(121.52,45.67) 121.36,45.83 121.36,47.39 121.81,47.85 122.15,47.85 arc(122.23,47.81) 122.26,47.73 arc(122.3,47.65) 122.38,47.62 122.58,47.62 arc(122.66,47.65) 122.69,47.73 arc(122.73,47.81) 122.81,47.85 123,47.85 arc(123.08,47.81) 123.12,47.73 arc(123.15,47.65) 123.23,47.62 123.43,47.62 arc(123.51,47.65) 123.54,47.73 arc(123.58,47.81) 123.66,47.85 125.39,47.85 125.49,47.75 J22.17 ; J4.83 40.11,71.01 40.05,70.95 40.05,69.93 38.71,68.59 36.61,68.59 34.53,66.51 34.53,54.45 33.83,53.75 33.83,52.9 v1(34.03,52.7)
  ART03 w0.102: v1(121.52,45.67) 121.38,45.81 121.38,46.21 121.03,46.56 119.02,46.56 116.3,49.27 101.16,49.27 101.06,49.38 101.06,49.91 100.8,50.17 100.26,50.17 99.99,49.91 99.99,49.38 99.89,49.27 99.59,49.27 99.49,49.38 99.49,49.97 99.21,50.26 98.68,50.26 98.42,49.99 98.42,49.53 98.32,49.43 74.27,49.43 71.63,52.07 43.69,52.07 43.05,51.43 34.21,51.43 33.82,51.83 33.82,52.49 v1(34.03,52.7)
MIPI_DPHY1_RX_D2P: length 125.1
  TOP w0.107: J4.81 39.71,71.01 39.77,70.95 39.77,70.05 38.59,68.87 36.49,68.87 34.24,66.63 34.24,54.56 33.55,53.87 33.55,52.88 v1(33.37,52.7) ; v1(120.86,45.67) 121.07,45.89 121.07,47.51 121.69,48.13 125.4,48.13 125.52,48.25 J22.16
  ART03 w0.102: v1(33.37,52.7) 33.54,52.54 33.54,51.72 34.1,51.15 43.17,51.15 43.8,51.79 71.52,51.79 74.16,49.15 98.43,49.15 98.7,49.41 98.7,49.87 98.8,49.98 99.09,49.98 99.21,49.86 99.21,49.26 99.47,49 100.01,49 100.27,49.26 100.27,49.79 100.38,49.89 100.68,49.89 100.78,49.79 100.78,49.26 101.05,49 116.19,49 118.9,46.28 120.92,46.28 121.1,46.1 121.1,45.91 v1(120.86,45.67)
MIPI_DPHY1_RX_D3N: length 125.2
  TOP w0.107: J4.79 39.31,71.01 39.25,70.95 39.25,70.12 38.42,69.29 35.95,69.29 33.26,66.59 33.26,65.18 arc(33.29,65.1) 33.37,65.06 arc(33.45,65.03) 33.49,64.95 33.49,64.75 arc(33.45,64.67) 33.37,64.64 arc(33.29,64.6) 33.26,64.52 33.26,64.32 arc(33.29,64.24) 33.37,64.21 arc(33.45,64.18) 33.49,64.1 33.49,63.9 arc(33.45,63.82) 33.37,63.78 arc(33.29,63.75) 33.26,63.67 33.26,55.97 32.1,54.81 32.1,52.86 v1(32.26,52.7) ; J22.20 125.45,46.25 125.24,46.47 123.93,46.47 123.2,45.73 123.2,44.34 v1(123.34,44.19)
  ART03 w0.102: v1(32.26,52.7) 32.07,52.51 32.07,51.88 33.3,50.65 43.46,50.65 43.99,51.18 70.6,51.18 73.39,48.39 116.1,48.39 119.33,45.16 122.81,45.16 123.16,44.8 123.16,44.37 v1(123.34,44.19)
MIPI_DPHY1_RX_D3P: length 125.2
  TOP w0.107: J22.19 123.81,46.75 122.91,45.85 122.91,44.42 v1(122.68,44.19) ; v1(31.6,52.7) 31.82,52.92 31.82,54.93 32.97,56.09 32.97,66.71 35.83,69.57 38.3,69.57 38.97,70.24 38.97,70.95 38.91,71.01 J4.77
  ART03 w0.102: v1(122.68,44.19) 122.89,44.4 122.89,44.68 122.69,44.88 119.22,44.88 115.99,48.11 73.28,48.11 70.48,50.9 44.11,50.9 43.58,50.37 33.18,50.37 31.79,51.76 31.79,52.51 v1(31.6,52.7)
MIPI_DPHY1_TX_CLKN: length 108.8
  TOP w0.107: J4.65 36.51,72.2 36.45,72.26 36.45,73.25 36.64,73.44 v1(36.64,73.84) ; v1(128.89,78.43) 128.89,78.42 128.66,78.19 127.36,78.19 127.31,78.25 J20.24
  ART03 w0.102: v1(36.64,73.84) 36.64,73.44 36.45,73.25 36.45,71.64 36.66,71.43 40.53,71.43 40.75,71.65 40.75,72.45 41.02,72.71 41.53,72.71 41.82,72.42 41.82,71.65 41.92,71.55 72.42,71.55 72.78,71.19 72.78,70.59 73.01,70.36 84.06,70.36 84.26,70.56 84.26,74.27 84.63,74.64 92.87,74.64 93.48,74.03 97.75,74.03 98.51,74.8 117.9,74.8 119.68,76.58 124.23,76.58 125.83,78.18 126.98,78.18 arc(127.03,78.2) 127.05,78.26 arc(127.08,78.31) 127.13,78.34 127.38,78.34 arc(127.44,78.31) 127.46,78.26 arc(127.48,78.2) 127.54,78.18 127.79,78.18 arc(127.84,78.2) 127.87,78.26 arc(127.89,78.31) 127.95,78.34 128.2,78.34 arc(128.25,78.31) 128.27,78.26 arc(128.3,78.2) 128.35,78.18 128.66,78.18 128.89,78.42 v1(128.89,78.43)
MIPI_DPHY1_TX_CLKP: length 108.9
  TOP w0.107: J4.63 36.11,72.2 36.17,72.26 36.17,73.25 35.98,73.44 v1(35.98,73.84) ; v1(128.89,77.77) 128.75,77.91 127.46,77.91 127.3,77.74 J20.23
  ART03 w0.102: v1(128.89,77.77) 128.85,77.77 128.79,77.82 128.75,77.82 128.67,77.9 125.95,77.9 124.35,76.3 119.79,76.3 118.01,74.52 98.63,74.52 97.86,73.76 93.36,73.76 92.76,74.36 84.74,74.36 84.54,74.16 84.54,70.44 84.17,70.08 72.89,70.08 72.5,70.47 72.5,71.07 72.3,71.27 41.8,71.27 41.54,71.54 41.54,72.31 41.41,72.43 41.13,72.43 41.03,72.33 41.03,71.54 40.64,71.15 36.55,71.15 36.17,71.52 36.17,73.25 35.98,73.44 v1(35.98,73.84)
MIPI_DPHY1_TX_D0N: length 108.9
  TOP w0.107: J4.73 38.11,72.2 38.05,72.26 38.05,73.28 38.24,73.46 v1(38.24,73.86) ; J20.27 127.31,79.74 127.39,79.66 128.69,79.66 v1(128.91,79.88)
  ART03 w0.102: v1(38.24,73.86) 38.24,73.47 38.05,73.27 38.05,73 38.39,72.66 39.36,72.66 40.18,73.48 58.66,73.48 58.86,73.68 58.86,75 59.14,75.27 61.01,75.27 61.28,75 61.28,73.93 61.38,73.83 61.69,73.83 61.79,73.93 61.79,75.01 62.06,75.27 62.58,75.27 62.86,75 62.86,73.93 62.96,73.83 63.26,73.83 63.37,73.93 63.37,75.01 63.63,75.27 64.17,75.27 64.43,75.01 64.43,74.4 64.53,74.3 64.84,74.3 64.94,74.4 64.94,75.01 65.21,75.27 65.74,75.27 66.01,75.01 66.01,74.4 66.11,74.3 66.41,74.3 66.52,74.4 66.52,75.01 66.78,75.27 72.45,75.27 73.46,76.28 118.38,76.28 119.36,77.27 123.57,77.27 125.96,79.65 127.04,79.65 arc(127.11,79.68) 127.13,79.74 arc(127.16,79.81) 127.22,79.84 127.45,79.84 arc(127.51,79.81) 127.54,79.74 arc(127.57,79.68) 127.63,79.65 127.85,79.65 arc(127.92,79.68) 127.95,79.74 arc(127.97,79.81) 128.04,79.84 128.26,79.84 arc(128.33,79.81) 128.35,79.74 arc(128.38,79.68) 128.44,79.65 128.68,79.65 v1(128.91,79.88)
MIPI_DPHY1_TX_D0P: length 108.9
  TOP w0.107: v1(37.58,73.86) 37.58,73.46 37.77,73.28 37.77,72.26 37.71,72.2 J4.71 ; v1(128.91,79.22) 128.75,79.38 127.44,79.38 127.31,79.25 J20.26
  ART03 w0.102: v1(128.91,79.22) 128.75,79.37 126.07,79.37 123.69,76.99 119.48,76.99 118.49,76 73.57,76 72.57,75 66.9,75 66.79,74.89 66.79,74.28 66.53,74.02 65.99,74.02 65.73,74.28 65.73,74.89 65.63,75 65.32,75 65.22,74.89 65.22,74.28 64.95,74.02 64.42,74.02 64.15,74.28 64.15,74.89 64.05,75 63.75,75 63.64,74.89 63.64,73.82 63.38,73.55 62.84,73.55 62.58,73.82 62.58,74.88 62.47,75 62.17,75 62.07,74.89 62.07,73.82 61.8,73.55 61.27,73.55 61,73.82 61,74.88 60.89,75 59.25,75 59.14,74.88 59.14,73.57 58.77,73.2 40.29,73.2 39.48,72.38 38.27,72.38 37.77,72.88 37.77,73.27 37.58,73.47 v1(37.58,73.86)
MIPI_DPHY1_TX_D1N: length 108.8
  TOP w0.107: v1(37.42,70.34) 37.34,70.34 37.24,70.45 37.24,70.89 37.31,70.97 J4.69 ; J20.21 127.31,76.74 127.41,76.64 128.72,76.64 v1(128.91,76.83)
  ART03 w0.102: v1(37.42,70.34) 37.42,69.94 37.23,69.75 37.23,69.52 37.33,69.42 38.64,69.42 38.84,69.62 38.84,70.12 39.28,70.56 50.87,70.56 51.33,70.1 59.85,70.1 60.41,70.66 62.46,70.66 62.72,70.39 62.72,69.95 62.82,69.85 63.13,69.85 63.23,69.95 63.23,70.39 63.49,70.66 64.03,70.66 64.3,70.39 64.3,69.95 64.4,69.85 64.7,69.85 64.8,69.95 64.8,70.39 65.07,70.66 70.09,70.66 70.35,70.39 70.35,69.47 70.45,69.37 70.76,69.37 70.86,69.47 70.86,70.39 71.13,70.66 71.69,70.66 71.96,70.39 71.96,69.59 72.16,69.39 86.6,69.39 86.8,69.59 86.8,72.67 87.24,73.12 98.47,73.12 99.26,73.91 104.61,73.91 104.99,73.53 121.26,73.53 123.58,75.84 125.51,75.84 126.3,76.63 126.99,76.63 arc(127.05,76.66) 127.08,76.72 arc(127.1,76.79) 127.17,76.81 127.39,76.81 arc(127.46,76.79) 127.48,76.72 arc(127.51,76.66) 127.57,76.63 127.8,76.63 arc(127.86,76.66) 127.89,76.72 arc(127.92,76.79) 127.98,76.81 128.21,76.81 arc(128.27,76.79) 128.3,76.72 arc(128.32,76.66) 128.39,76.63 128.71,76.63 v1(128.91,76.83)
MIPI_DPHY1_TX_D1P: length 108.9
  TOP w0.107: v1(128.91,76.16) 128.72,76.35 127.41,76.35 127.31,76.25 J20.20 ; J4.67 36.91,70.97 36.95,70.93 36.95,70.45 36.85,70.34 v1(36.76,70.34)
  ART03 w0.102: v1(36.76,70.34) 36.76,69.94 36.95,69.75 36.95,69.41 37.21,69.14 38.75,69.14 39.12,69.51 39.12,70.01 39.39,70.28 50.75,70.28 51.21,69.82 59.96,69.82 60.52,70.38 62.34,70.38 62.44,70.28 62.44,69.83 62.71,69.57 63.24,69.57 63.51,69.83 63.51,70.28 63.61,70.38 63.91,70.38 64.02,70.28 64.02,69.83 64.28,69.57 64.82,69.57 65.08,69.83 65.08,70.28 65.18,70.38 69.97,70.38 70.07,70.28 70.07,69.36 70.34,69.09 70.88,69.09 71.14,69.36 71.14,70.27 71.25,70.38 71.58,70.38 71.68,70.28 71.68,69.48 72.05,69.11 86.71,69.11 87.08,69.48 87.08,72.56 87.36,72.84 98.58,72.84 99.37,73.63 104.49,73.63 104.87,73.25 121.38,73.25 123.7,75.56 125.63,75.56 126.42,76.36 128.71,76.36 v1(128.91,76.16)
MIPI_DPHY1_TX_D2N: length 108.8
  TOP w0.107: v1(128.91,75.21) 128.73,75.04 128.39,75.04 128.31,75.11 127.44,75.11 127.31,75.25 J20.18 ; v1(35.82,70.34) 35.74,70.34 35.64,70.45 35.64,70.89 35.71,70.97 J4.61
  ART03 w0.102: v1(128.91,75.21) 128.7,75 128.47,75 arc(128.41,75.03) 128.39,75.08 arc(128.37,75.14) 128.31,75.16 128.06,75.16 arc(128.01,75.14) 127.98,75.08 arc(127.96,75.03) 127.9,75 127.66,75 arc(127.6,75.03) 127.58,75.08 arc(127.55,75.14) 127.5,75.16 127.25,75.16 arc(127.19,75.14) 127.17,75.08 arc(127.15,75.03) 127.09,75 126.78,75 125.46,73.68 124.04,73.68 122.03,71.68 88.35,71.68 87.8,71.13 87.8,68.36 87.67,68.23 70.32,68.23 69.64,68.9 51.31,68.9 50.5,69.72 43.51,69.72 43.19,69.4 43.19,68.71 43.08,68.6 42.78,68.6 42.68,68.7 42.68,69.4 42.42,69.67 41.88,69.67 41.61,69.4 41.61,68.71 41.51,68.6 41.21,68.6 41.11,68.7 41.11,69.4 40.84,69.67 40.29,69.67 39.95,69.33 39.95,68.67 39.85,68.57 35.81,68.57 35.63,68.75 35.63,69.75 35.82,69.94 v1(35.82,70.34)
MIPI_DPHY1_TX_D2P: length 108.8
  TOP w0.107: v1(35.16,70.34) 35.25,70.34 35.35,70.45 35.35,70.93 35.31,70.97 J4.59 ; v1(128.91,74.55) 128.7,74.75 128.27,74.75 128.19,74.83 127.39,74.83 127.31,74.74 J20.17
  ART03 w0.102: v1(128.91,74.55) 128.73,74.72 126.9,74.72 125.58,73.4 124.16,73.4 122.15,71.4 88.47,71.4 88.08,71.01 88.08,68.24 87.79,67.95 70.2,67.95 69.53,68.62 51.2,68.62 50.38,69.44 43.63,69.44 43.47,69.29 43.47,68.59 43.2,68.32 42.66,68.32 42.4,68.59 42.4,69.29 42.29,69.39 42,69.39 41.89,69.29 41.89,68.59 41.62,68.32 41.09,68.32 40.83,68.59 40.83,69.29 40.73,69.39 40.4,69.39 40.23,69.21 40.23,68.55 39.96,68.29 35.7,68.29 35.35,68.64 35.35,69.75 35.16,69.94 v1(35.16,70.34)
MIPI_DPHY1_TX_D3N: length 108.8
  TOP w0.107: J20.30 127.31,81.25 127.38,81.18 128.67,81.18 v1(128.91,81.41) ; v1(35.04,73.84) 35.04,73.44 34.85,73.25 34.85,72.26 34.91,72.2 J4.57
  ART03 w0.102: v1(128.91,81.41) 128.84,81.34 126.37,81.34 123.04,78 119.01,78 118.16,77.15 59.12,77.15 57.47,75.5 33.72,75.5 33.11,74.89 33.11,72.65 33.47,72.29 34.38,72.29 34.85,72.76 34.85,73.25 35.04,73.44 v1(35.04,73.84)
MIPI_DPHY1_TX_D3P: length 108.8
  TOP w0.107: J20.29 127.31,80.74 127.45,80.89 128.76,80.89 v1(128.91,80.75) ; J4.55 34.51,72.2 34.57,72.26 34.57,73.25 34.38,73.44 v1(34.38,73.84)
  ART03 w0.102: v1(128.91,80.75) 128.59,81.06 126.49,81.06 123.15,77.72 119.13,77.72 118.27,76.87 59.23,76.87 57.59,75.22 38.17,75.22 arc(38.09,75.19) 38.06,75.11 arc(38.03,75.04) 37.95,75.01 37.76,75.01 arc(37.68,75.04) 37.65,75.11 arc(37.62,75.19) 37.54,75.22 37.36,75.22 arc(37.28,75.19) 37.25,75.11 arc(37.21,75.04) 37.14,75.01 36.95,75.01 arc(36.87,75.04) 36.84,75.11 arc(36.81,75.19) 36.73,75.22 36.54,75.22 arc(36.47,75.19) 36.43,75.11 arc(36.4,75.04) 36.32,75.01 36.14,75.01 arc(36.06,75.04) 36.03,75.11 arc(36,75.19) 35.92,75.22 35.73,75.22 arc(35.65,75.19) 35.62,75.11 arc(35.59,75.04) 35.51,75.01 35.32,75.01 arc(35.25,75.04) 35.21,75.11 arc(35.18,75.19) 35.11,75.22 34.92,75.22 arc(34.84,75.19) 34.81,75.11 arc(34.78,75.04) 34.7,75.01 34.51,75.01 arc(34.43,75.04) 34.4,75.11 arc(34.37,75.19) 34.29,75.22 33.84,75.22 33.39,74.77 33.39,72.77 33.59,72.57 34.27,72.57 34.57,72.87 34.57,73.25 34.38,73.44 v1(34.38,73.84)
OTG_DM: length 32.5
  TOP w0.135: R221.1 33.88,92.16 33.88,93.75 D36.1 33.88,94.96 33.88,95.22 34.24,95.59 35.07,95.59 35.33,95.84 35.33,99.19 35.04,99.48 31.61,99.48 31.02,100.07 28.89,100.07 28.3,99.48 28.3,98.72 v1(28.47,98.55) 28.29,98.37 28.29,98.18 28.38,98.1 J30.B7 ; J30.A7 27.62,94.8 27.44,94.62 27.44,93.99 v1(27.18,93.72)
  ART03 w0.135: v1(27.18,93.72) 27.3,93.85 27.3,94.1 27.17,94.23 26.59,94.23 25.96,94.87 25.96,99.71 26.5,100.25 27.82,100.25 28.38,99.69 28.38,98.64 v1(28.47,98.55)
OTG_DP: length 33.6
  TOP w0.135: R220.1 34.19,92.16 34.19,93.75 D35.1 34.19,94.96 34.19,95.09 34.37,95.27 35.2,95.27 35.64,95.71 35.64,99.32 35.17,99.8 31.74,99.8 31.15,100.39 28.76,100.39 27.99,99.61 27.99,98.72 v1(27.81,98.55) 27.98,98.38 27.98,98.19 27.88,98.1 J30.B6 ; v1(27.84,93.72) 27.75,93.81 27.75,94.49 27.93,94.67 27.93,95.24 28.12,95.43 J30.A6
  ART03 w0.135: v1(27.81,98.55) 28.07,98.8 28.07,99.56 27.69,99.94 26.63,99.94 26.27,99.58 26.27,98.32 arc(26.31,98.22) 26.41,98.18 arc(26.5,98.14) 26.54,98.04 26.54,97.78 arc(26.5,97.68) 26.41,97.64 arc(26.31,97.6) 26.27,97.51 26.27,97.24 arc(26.31,97.14) 26.41,97.1 arc(26.5,97.06) 26.54,96.97 26.54,96.7 arc(26.5,96.61) 26.41,96.57 arc(26.31,96.53) 26.27,96.43 26.27,96.16 arc(26.31,96.07) 26.41,96.03 arc(26.5,95.99) 26.54,95.89 26.54,95.62 arc(26.5,95.53) 26.41,95.49 arc(26.31,95.45) 26.27,95.35 26.27,95 26.72,94.55 27.3,94.55 27.61,94.23 27.61,93.95 v1(27.84,93.72)
OUT1_L: length 27
  TOP w0.254: v1(45.59,62.48) 44.65,61.54 40.94,61.54 40.39,62.1 40.39,65.38 v1(40.34,65.43)
  BOTTOM w0.203: U33.12 48.32,65.21 v1(45.59,62.48)
  BOTTOM w0.254: C191.1 40.34,77.67 v1(40.34,65.43)
OUT1_R: length 29.6
  TOP w0.254: v1(39.07,65.43) 39.12,65.43 39.62,64.92 39.62,61.72 40.39,60.96 44.96,60.96 v1(46.48,62.48)
  BOTTOM w0.203: v1(46.48,62.48) 48.77,64.77 U33.11
  BOTTOM w0.254: C193.1 38.74,77.24 39.4,76.58 39.4,65.76 v1(39.07,65.43)
OUT2_L: length 26.2
  BOTTOM w0.203: R203.1 31.62,69.09 32.38,68.32 32.38,64.77 32.74,64.41 44.86,64.41 46.1,65.66 46.1,66.77 46.3,66.97 U33.15
OUT2_R: length 27.6
  BOTTOM w0.203: U33.14 47.42,66.09 45.11,63.78 32.48,63.78 31.75,64.51 31.75,67.56 30.61,68.71 R204.1
PCIE20_0_CLKN: length 110.2
  TOP w0.107: v1(52.28,26.6) 52.08,26.4 J5.16 ; v1(51.09,56.52) 50.96,56.65 50.96,57.81 54.48,61.34 67.5,61.34 72.8,66.64 91.4,66.64 92.84,68.07 92.84,72.09 93.67,72.92 98.78,72.92 100.47,74.61 104.3,74.61 105.37,75.68 114.06,75.68 115.36,76.98 115.36,77.71 115.6,77.95 J25.11
  BOTTOM w0.107: v1(52.28,26.6) 52.28,26.99 52.07,27.2 52.07,28.33 51.42,28.97 51.42,54.37 50.93,54.86 50.93,56.38 51.07,56.52 v1(51.09,56.52)
PCIE20_0_CLKP: length 110.2
  TOP w0.107: J5.14 51.68,26.53 v1(51.61,26.6) ; J25.13 114.8,77.95 115.08,77.68 115.08,77.1 113.94,75.96 105.25,75.96 104.19,74.89 100.35,74.89 98.66,73.2 93.55,73.2 92.55,72.21 92.55,68.19 91.29,66.92 72.68,66.92 67.39,61.62 54.37,61.62 50.67,57.93 50.67,56.77 v1(50.43,56.52)
  BOTTOM w0.107: v1(51.61,26.6) 51.61,26.99 51.79,27.17 51.79,28.21 51.14,28.85 51.14,54.25 50.65,54.74 50.65,56.31 v1(50.43,56.52)
PCIE20_0_RXN: length 112.1
  TOP w0.15: J5.6 50.08,24.47 50.04,24.44 50.04,23.89 49.4,23.24 48.05,23.24 47.88,23.07 v1(47.48,23.07) ; J25.23 107.6,77.94 107.37,77.71 107.37,77.16 106.79,76.58 104.84,76.58 104.02,75.77 99.72,75.77 97.75,73.8 92.73,73.8 91.69,72.77 91.69,68.83 90.76,67.89 72.23,67.89 67.05,62.71 54.33,62.71 48.77,57.15 48.77,55.88 v1(48.9,55.75)
  BOTTOM w0.15: v1(48.9,55.75) 48.77,55.62 48.77,54.44 49.86,53.36 49.86,23.95 49.15,23.24 48.05,23.24 47.88,23.07 v1(47.48,23.07)
